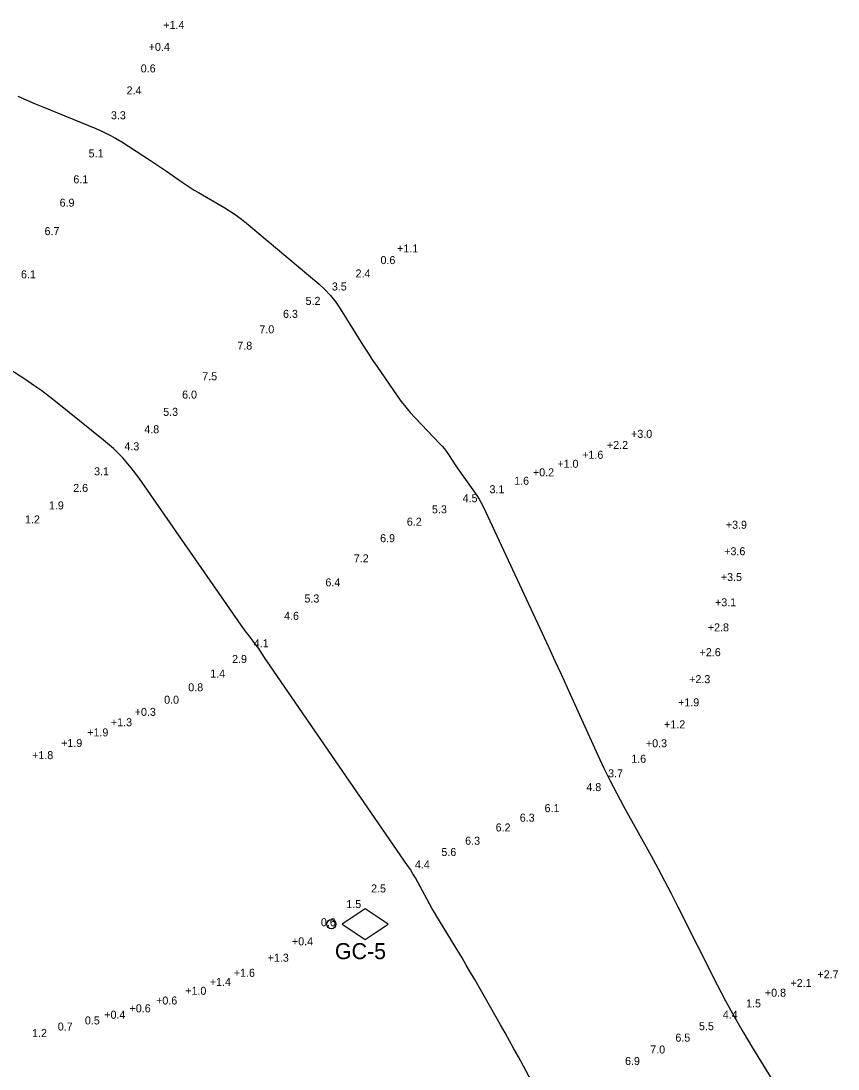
# Model space of a CAD drawing. Extents: x 837127 to 848654, y 3074248 to 3079868.
# Drawn here: x 845553.7 to 845872.6, y 3078632.8 to 3079042 of the extents above; entities that cross this region are included whole.
import ezdxf

# ---------------------------------------------------------------- set-up
doc = ezdxf.new("R2010")
doc.units = 0
for name, color, linetype in [('V-CHAN-NAID', 7, 'Continuous'), ('V-HYDS-MAJR', 7, 'Continuous'), ('V-HYDS-SOUN', 7, 'Continuous'), ('V-HYDS-SOUN-EXSS', 7, 'Continuous')]:
    doc.layers.add(name, color=color, linetype=linetype)

msp = doc.modelspace()

# ---------------------------------------------------------------- linework, layer by layer
at = {"layer": 'V-CHAN-NAID'}
msp.add_lwpolyline([(845679.02, 3078689.39), (845688.02, 3078683.39), (845697.02, 3078689.39), (845688.02, 3078695.39)], close=True, dxfattribs=at)
msp.add_circle((845674.82, 3078689.39), 1.8, dxfattribs=at)
at = {"layer": 'V-HYDS-MAJR'}
for points in [[(845552.52, 3079012.6), (845555.76, 3079011.15), (845559.02, 3079009.75), (845562.3, 3079008.39), (845582.99, 3078999.96), (845585.59, 3078998.83), (845588.14, 3078997.58), (845590.63, 3078996.21), (845593.05, 3078994.73), (845604.27, 3078987.54), (845605.84, 3078986.52), (845607.41, 3078985.48), (845608.96, 3078984.43), (845610.51, 3078983.36), (845616.66, 3078979.05), (845618.21, 3078977.99), (845619.78, 3078976.96), (845621.37, 3078975.97), (845622.98, 3078975), (845633.27, 3078968.99), (845635.5, 3078967.62), (845637.66, 3078966.17), (845639.75, 3078964.62), (845641.78, 3078962.99), (845669.91, 3078939.36), (845672.34, 3078937.14), (845674.57, 3078934.76), (845676.6, 3078932.2), (845678.43, 3078929.48), (845685.41, 3078918.16), (845687.14, 3078915.39), (845688.91, 3078912.64), (845690.71, 3078909.91), (845692.55, 3078907.2), (845700.53, 3078895.61), (845702.14, 3078893.36), (845703.85, 3078891.17), (845705.65, 3078889.06), (845707.53, 3078887.02), (845717.22, 3078876.93), (845718.13, 3078875.94), (845718.98, 3078874.92), (845719.78, 3078873.86), (845720.54, 3078872.76), (845723.46, 3078868.27), (845724.2, 3078867.15), (845724.95, 3078866.05), (845725.71, 3078864.95), (845726.49, 3078863.86), (845730.73, 3078858.03), (845731.66, 3078856.67), (845732.53, 3078855.28), (845733.32, 3078853.85), (845734.05, 3078852.37), (845759.66, 3078797.37), (845762.07, 3078792.17), (845764.47, 3078786.96), (845766.86, 3078781.75), (845769.24, 3078776.54), (845778.87, 3078755.34), (845781.22, 3078750.31), (845783.66, 3078745.32), (845786.2, 3078740.39), (845788.84, 3078735.5), (845799.59, 3078716.05), (845802.25, 3078711.18), (845804.87, 3078706.28), (845807.44, 3078701.36), (845809.97, 3078696.41), (845825.47, 3078665.67), (845828.7, 3078659.43), (845832.06, 3078653.27), (845835.55, 3078647.17), (845839.17, 3078641.15), (845859.66, 3078607.91)], [(845754.65, 3078625), (845747.83, 3078637.58), (845746.12, 3078640.72), (845744.39, 3078643.84), (845742.64, 3078646.96), (845740.87, 3078650.07), (845730.78, 3078667.75), (845729.16, 3078670.57), (845727.51, 3078673.37), (845725.86, 3078676.17), (845724.18, 3078678.95), (845716.05, 3078692.34), (845715.07, 3078693.99), (845714.1, 3078695.65), (845713.16, 3078697.32), (845712.24, 3078699), (845708.61, 3078705.76), (845707.67, 3078707.44), (845706.7, 3078709.09), (845705.68, 3078710.71), (845704.61, 3078712.3), (845651.01, 3078790.17), (845650.55, 3078790.85), (845650.09, 3078791.52), (845649.64, 3078792.2), (845649.19, 3078792.88), (845647.41, 3078795.62), (845646.96, 3078796.3), (845646.49, 3078796.97), (845646.02, 3078797.63), (845645.53, 3078798.28), (845642.36, 3078802.4), (845641.67, 3078803.31), (845640.99, 3078804.23), (845640.33, 3078805.15), (845639.67, 3078806.08), (845599.85, 3078863.48), (845596.78, 3078867.58), (845593.44, 3078871.43), (845589.84, 3078875.02), (845585.97, 3078878.37), (845567.83, 3078892.95), (845564.85, 3078895.29), (845561.81, 3078897.55), (845558.71, 3078899.72), (845555.56, 3078901.82), (845537.47, 3078913.53)]]:
    msp.add_lwpolyline(points, dxfattribs=at)

# ---------------------------------------------------------------- texts
at = {"layer": 'V-CHAN-NAID'}
msp.add_text('GC-5', height=6.25, dxfattribs=at).set_placement((845676.23, 3078675.72))
at = {"layer": 'V-HYDS-SOUN'}
for s, p in [('+1.4 ', (845609.26, 3079038.85)), ('+0.4 ', (845603.58, 3079030.3)), ('0.6', (845600.46, 3079021.89)), ('2.4', (845594.95, 3079013.31)), ('3.3', (845588.83, 3079003.6)), ('5.1', (845580.13, 3078988.71)), ('6.1', (845574.17, 3078978.6)), ('6.9', (845568.8, 3078969.46)), ('6.7', (845562.93, 3078958.36)), ('+1.1 ', (845700.49, 3078951.61)), ('0.6', (845694.03, 3078947.06)), ('6.1', (845553.74, 3078941.49)), ('2.4', (845684.3, 3078941.84)), ('3.5', (845675.04, 3078936.76)), ('5.2', (845664.79, 3078931.13)), ('6.3', (845655.99, 3078926.07)), ('7.0', (845646.77, 3078920.04)), ('7.8', (845638.16, 3078913.65)), ('7.5', (845624.46, 3078901.71)), ('6.0', (845616.61, 3078894.55)), ('5.3', (845609.21, 3078887.82)), ('4.8', (845601.85, 3078881.02)), ('+3.0 ', (845791.81, 3078879.22)), ('4.3', (845594.08, 3078874.37)), ('+2.2 ', (845782.4, 3078874.88)), ('+1.6 ', (845772.73, 3078871.05)), ('+1.0 ', (845763.03, 3078867.54)), ('3.1', (845582.27, 3078864.6)), ('+0.2 ', (845753.53, 3078864.19)), ('2.6', (845574.11, 3078858.11)), ('3.1', (845736.57, 3078857.61)), ('1.6', (845746.18, 3078860.9)), ('4.5', (845726.08, 3078854.11)), ('1.9', (845564.63, 3078851.28)), ('5.3', (845714.11, 3078849.75)), ('1.2', (845555.3, 3078845.83)), ('6.2', (845704.3, 3078844.92)), ('+3.9 ', (845828.78, 3078843.74)), ('6.9', (845693.88, 3078838.5)), ('+3.6 ', (845828.16, 3078833.4)), ('7.2', (845683.61, 3078830.62)), ('6.4', (845672.54, 3078821.25)), ('+3.5 ', (845826.84, 3078823.32)), ('5.3', (845664.35, 3078814.95)), ('+3.1 ', (845824.56, 3078813.46)), ('4.6', (845656.4, 3078808.19)), ('+2.8 ', (845821.77, 3078803.67)), ('4.1', (845644.57, 3078797.5)), ('+2.6 ', (845818.55, 3078793.99)), ('2.9', (845636.11, 3078791.33)), ('1.4', (845627.6, 3078785.65)), ('0.8', (845619.01, 3078780.29)), ('+2.3 ', (845814.48, 3078783.46)), (' 0.0', (845608.43, 3078775.43)), ('+1.9 ', (845810.16, 3078774.4)), ('+0.3 ', (845598.12, 3078770.69)), ('+1.3 ', (845588.83, 3078766.64)), ('+1.2 ', (845804.69, 3078765.81)), ('+1.9 ', (845579.58, 3078762.68)), ('+1.9 ', (845569.39, 3078758.53)), ('+0.3 ', (845797.6, 3078758.43)), ('+1.8 ', (845558.07, 3078753.8)), ('1.6', (845791.87, 3078752.39)), ('3.7', (845782.85, 3078746.69)), ('4.8', (845774.36, 3078741.32)), ('6.1', (845758.06, 3078733.1)), ('6.3', (845748.37, 3078729.39)), ('6.2', (845738.96, 3078725.57)), ('6.3', (845727.06, 3078720.38)), ('5.6', (845717.79, 3078715.98)), ('4.4', (845707.45, 3078711.11)), ('2.5', (845690.37, 3078701.76)), ('1.5', (845680.7, 3078695.66)), ('+0.4 ', (845659.48, 3078681.12)), ('+1.3 ', (845649.99, 3078674.7)), ('+1.4 ', (845627.41, 3078665.28)), ('+1.6 ', (845636.78, 3078668.83)), ('+2.1 ', (845854.02, 3078664.85)), ('+2.7 ', (845864.53, 3078668.23)), ('+1.0 ', (845617.83, 3078661.81)), ('+0.8 ', (845844.03, 3078661.05)), ('+0.6 ', (845606.46, 3078658.01)), ('1.5', (845836.7, 3078656.88)), ('+0.6 ', (845596.1, 3078654.95)), ('0.5', (845578.67, 3078650.24)), ('+0.4 ', (845586.23, 3078652.48)), ('4.4', (845827.61, 3078652.52)), ('1.2', (845558.05, 3078645.31)), ('0.7', (845568.09, 3078647.84)), ('5.5', (845818.31, 3078647.99)), ('6.5', (845809.1, 3078643.52)), ('7.0', (845799.29, 3078638.89)), ('6.9', (845789.45, 3078634.4))]:
    msp.add_text(s, height=3.125, dxfattribs=at).set_placement(p)
at = {"layer": 'V-HYDS-SOUN-EXSS'}
msp.add_text('0.6', height=3.125, dxfattribs=at).set_placement((845670.78, 3078688.57))

doc.saveas('drawing.dxf')
